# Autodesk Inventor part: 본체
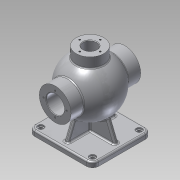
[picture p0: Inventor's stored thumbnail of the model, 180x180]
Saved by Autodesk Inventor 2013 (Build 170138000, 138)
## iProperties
Created: 2018-06
Part Number: 본체
Material: 알루미늄 6061
Document SubType Name: Modeling
Designer: Administrator
Density: 2.71 g/cm^3
Mass: 1509.81 g
Surface Area: 1154.15 cm^2
Volume: 557.126 cm^3
Author: Administrator
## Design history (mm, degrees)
sketch "스케치1"
  geometry: L1 (0, 53)-(0, -53); A1 r 53 centre (0, 0) between (0, -53) and (0, 53); A2 r 43 centre (0, 0) between (0, -43) and (0, 43); 1 further point
  constraints: 4 point on circle, 2 centre point, 2 coincident, 2 end point, 2 point on line, 1 midpoint, 1 vertical
  dimensions: "d0" = 53 radius of A1; "d1" = 43 radius of A2
revolve "회전1" sketch "스케치1" stored, may be unused: angle "d2" = 90 deg
node "작업 평면1"
sketch "스케치2"
  geometry: C1 r 31 at (0, 0); 1 further point
  constraints: 1 centre point, 1 coincident
  dimensions: "d4" = 62 diameter of C1
extrude "돌출1" join sketch "스케치2" stored distance "d5" = 10; taper "d6" = 0 deg
hole "구멍1" diameter "d9" = 35; stored, may be unused: countersink angle "d13" = 90 deg, drill point angle "d15" = 118 deg; dims "d7" = 10, "d8" = 10, "d10" = 6, "d11" = 4, "d12" = 2, "d14" = 8
node "작업 평면2"
sketch "스케치3"
  geometry: C1 r 27 at (0, 0); 1 further point
  constraints: 1 centre point, 1 coincident
  dimensions: "d17" = 54 diameter of C1
extrude "돌출2" join sketch "스케치3" stored distance "d18" = 10; taper "d19" = 0 deg
hole "구멍2" diameter "d22" = 26; stored, may be unused: countersink angle "d26" = 90 deg, drill point angle "d28" = 118 deg; dims "d23" = 6, "d24" = 4, "d25" = 2, "d27" = 8, "d48" = 10, "d49" = 10
node "작업 평면3"
sketch "스케치4"
  geometry: L1 (-62.5, -57.5)-(62.5, -57.5); L2 (62.5, -57.5)-(62.5, 57.5); L3 (62.5, 57.5)-(-62.5, 57.5); L4 (-62.5, 57.5)-(-62.5, -57.5); L5 (-62.5, -57.5)-(62.5, 57.5); L6 (62.5, -57.5)-(-62.5, 57.5); 1 further point
  constraints: 12 end point, 2 midpoint, 2 parallel, 1 horizontal, 1 perpendicular
  dimensions: "d30" = 125 distance of L2.end L3.end; "d32" = 115 distance of L1.end L2.end
extrude "돌출3" join sketch "스케치4" distance "d33" = 10; taper "d34" = 0 deg
fillet "모깎기1" dims "d35" = 12
sketch "스케치5"
  geometry: A1 r 12 centre (-50.5, 45.5) between (-50.5, 57.5) and (-62.5, 45.5) reference; A2 r 12 centre (-50.5, -45.5) between (-62.5, -45.5) and (-50.5, -57.5) reference; A3 r 12 centre (50.5, -45.5) between (50.5, -57.5) and (62.5, -45.5) reference; A4 r 12 centre (50.5, 45.5) between (62.5, 45.5) and (50.5, 57.5) reference; 5 further points
  constraints: 4 coincident
hole "구멍3" sketch "스케치5" at (-50.5, 45.5), (-50.5, -45.5), (50.5, -45.5), (50.5, 45.5) diameter "d36" = 8; stored, may be unused: countersink angle "d40" = 90 deg, drill point angle "d42" = 118 deg; dims "d37" = 6, "d38" = 12, "d39" = 3, "d41" = 8
sketch "스케치9"
  geometry: L1 (50.5, 57.5)-(-50.5, 57.5) reference; L2 (-4, -47.5)-(4, -47.5); L3 (4, -47.5)-(4, 47.5); L4 (4, 47.5)-(-4, 47.5); L5 (-4, 47.5)-(-4, -47.5); L6 (-4, -47.5)-(4, 47.5); L7 (4, -47.5)-(-4, 47.5); 1 further point
  constraints: 12 end point, 2 midpoint, 2 parallel, 1 horizontal, 1 perpendicular
  dimensions: "d52" = 8 distance of L3.end L4.end; "d54" = 10 distance between parallel lines of L1 L4
extrude "돌출4" join sketch "스케치9" stored distance "d55" = 10; taper "d56" = 0 deg
feature "면 기울기1" dims angle "d57" = 22 deg
feature "면 기울기2" dims angle "d58" = 22 deg
sketch "스케치10"
  geometry: L1 (62.5, -45.5)-(62.5, 45.5) reference; L2 (-52.5, -4)-(52.5, -4); L3 (52.5, -4)-(52.5, 4); L4 (52.5, 4)-(-52.5, 4); L5 (-52.5, 4)-(-52.5, -4); L6 (-52.5, -4)-(52.5, 4); L7 (52.5, -4)-(-52.5, 4); 1 further point
  constraints: 12 end point, 2 midpoint, 2 parallel, 1 horizontal, 1 perpendicular
  dimensions: "d59" = 8 distance of L2.end L3.end; "d61" = 10 distance between parallel lines of L1 L3
extrude "돌출5" join sketch "스케치10" stored distance "d62" = 10; taper "d63" = 0 deg
feature "면 기울기3" dims angle "d64" = 22 deg
feature "면 기울기4" dims angle "d65" = 22 deg
sketch "스케치11"
  geometry: C1 r 17.5 at (0, 0) reference; 1 further point
  constraints: 1 vertical alignment
  dimensions: "d66" = 22.5 distance of C1.centre point (0, 22.5)
hole "구멍4" sketch "스케치11" at (0, 22.5) diameter "d67" = 3.242; stored, may be unused: countersink angle "d71" = 90 deg, drill point angle "d73" = 118 deg; dims "d68" = 12, "d69" = 12, "d70" = 3, "d72" = 15
sketch "스케치12"
  geometry: C1 r 17.5 at (0, 0) reference; 1 further point
  constraints: 1 vertical alignment
  dimensions: "d77" = 24 distance of C1.centre point (0, -24)
hole "구멍5" sketch "스케치12" at (0, -24) diameter "d78" = 3.242; stored, may be unused: countersink angle "d82" = 90 deg, drill point angle "d84" = 118 deg; dims "d79" = 16, "d80" = 12, "d81" = 3, "d83" = 19
sketch "스케치13"
  geometry: C1 r 13 at (0, 0) reference; 1 further point
  constraints: 1 vertical alignment
  dimensions: "d88" = 20 distance of C1.centre point (0, 20)
hole "구멍6" sketch "스케치13" at (0, 20) diameter "d89" = 3.242; stored, may be unused: countersink angle "d93" = 90 deg, drill point angle "d95" = 118 deg; dims "d90" = 9, "d91" = 12, "d92" = 3, "d94" = 11
sketch "스케치14"
  geometry: L1 (50.25, 18.5)-(52, 18.5); L2 (52, 18.5)-(52, 0); L3 (52, 0)-(50.25, 0); L4 (50.25, 0)-(50.25, 18.5); L5 (68, 17.5)-(68, -17.5) reference; 1 further point
  constraints: 8 end point, 2 parallel, 1 horizontal, 1 perpendicular, 1 point on line
  dimensions: "d99" = 1.75 distance of L1.start L1.end; "d101" = 37 diameter of L1 L3; "d102" = 16 distance between parallel lines of L5 L2
revolve "회전2" sketch "스케치14" stored, may be unused: angle "d103" = 90 deg
fillet "모깎기3" dims "d105" = 3
fillet "모깎기4" dims "d106" = 3
node "작업 평면4"
sketch "스케치15"
  geometry: L1 (-27, 65)-(27, 65) reference; 2 further points
  constraints: 1 vertical alignment, 1 other
  dimensions: "d108" = 10 distance from line of L1 point (0, 55)
feature "엠보싱1" sketch "스케치15" dims "d17" = 54, "d109" = 0.5, "d110" = 0
chamfer "모따기1" distance "d111" = 1; stored, may be unused: second distance "d112" = 2, angle "d113" = 45 deg
node "솔리드1"
mirror "대칭1"
pattern_circular "원형 패턴1" dims angle "d75" = 360 deg
pattern_circular "원형 패턴2" dims angle "d86" = 360 deg
pattern_circular "원형 패턴3" dims angle "d97" = 360 deg
other parameters: "d3" = -68, "d16" = 65, "d29" = -85, "d107" = -27
